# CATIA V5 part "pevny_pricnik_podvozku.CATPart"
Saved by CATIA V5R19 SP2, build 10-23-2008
Part number: pevný příčník podvozku
Bounding box of the stored display mesh (mm): x -30 to 1210, y -1565 to 1565, z -174.111 to 167
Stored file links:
  D:\Catia fórum\Modely - Otazky\Naklapeni_oprava\pevny_pricnik_podvozku.CATPart
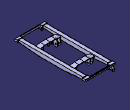
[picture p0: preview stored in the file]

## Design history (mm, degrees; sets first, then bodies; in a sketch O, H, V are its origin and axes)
Body1 (main body)
  Sketch1 on yz-plane, origin (0, 0, 0), H (0, 1, 0), V (0, 0, 1)
    construction line L1 (0, 0) -> (0, 143.6319)
    point P1 (0, 143.6319)
    line L2 (0, 160) -> (-1350, 160)
    point P2 (0, 160)
    point P3 (-1350, 160)
    line L3 (-1350, 160) -> (-1350, 74.3654)
    point P4 (-1350, 74.3654)
    line L4 (-1350, 74.3654) -> (-500, 0)
    point P5 (-500, 0)
    line L5 (-500, 0) -> (0, 0)
    point P6 (0, 143.6319)
    point P7 (0, 160)
    point P8 (0, 0)
    point P9 (500, 0)
    line L6 (500, 0) -> (0, 0)
    point P10 (1350, 74.3654)
    line L7 (1350, 74.3654) -> (500, 0)
    point P11 (1350, 160)
    line L8 (1350, 160) -> (1350, 74.3654)
    line L9 (0, 160) -> (1350, 160)
    distance L3 L1 = 1350
    distance P5 L1 = 500
    distance L5 L2 = 160
    angle L4 L5 = 175
    vertical: L1 V, L3 V
    coincidence: P2 L1, P5 H, O P8, P2 P7
    horizontal: L2 H, L5 H
    symmetry: P1 P6 L1, P2 P7 L1, O P8 L1, P5 P9 L1, L5 L6 L1, P4 P10 L1, L4 L7 L1, P3 P11 L1, L3 L8 L1, L2 L9 L1
  Pad1: profile Sketch1, direction (1, 0, 0), length 140
  Shell1: IntOffset 10, Face face of Pad1 from Sketch1.L9, ExtOffset 0
  Sketch2 on face of Shell1, origin (0, -1340, 0), H (-1, 0, 0), V (0, 0, 1)
    line L1 (-130, 160) -> (-10, 160)
    line L2 (-10, 160) -> (-10, 150)
    line L3 (-10, 150) -> (-130, 150)
    line L4 (-130, 150) -> (-130, 160)
    reference projected line E1 (-10, 160) -> (-130, 160) from edge [face of Pad1 from Sketch1.L2 | face of Shell1]
    reference projected line E2 (-130, 160) -> (-130, 83.5287) from edge [face of Shell1 | face of Shell1]
    reference projected line E3 (-10, 160) -> (-10, 83.5287) from edge [face of Shell1 | face of Shell1]
    distance L3 L1 = 10
    horizontal: L1 H, L3 H
    vertical: L2 V, L4 V
    coincidence: L1 E1, L4 E2, E3 L2
  Pad2: profile Sketch2, direction (0, 1, 0), up to the existing solid (limit type 2)
  Plane1: type Offset, RefPlane face of Pad1 from Sketch1.L3, Offset 550
  Sketch3 on Plane1, origin (0, -800, 0), H (-1, 0, 0), V (0, 0, 1)
    line L1 (-366.8513, 160) -> (-590, 160)
    point P1 (-590, 160)
    point P2 (-590, 140)
    line L2 (-590, 140) -> (-368.601, 140)
    point P3 (-368.601, 140)
    line L3 (-368.601, 140) -> (-140, 99.6915)
    reference projected line E1 (0, 160) -> (-140, 160) from edge [face of Pad1 from Sketch1.L3 | face of Pad1 from Sketch1.L2]
    line L4 (-366.8513, 160) -> (-140, 120)
    point P4 (-366.8513, 160)
    line L5 (-140, 120) -> (-140, 99.6915)
    point P5 (-140, 120)
    point P6 (-140, 99.6915)
    reference projected line E2 (-140, 160) -> (-140, 74.3654) from edge [face of Pad1 from Sketch1.L3 | end face of Pad1]
    construction line L6 (-590, 160) -> (-590, -11.9154)
    point P8 (-590, 160)
    point P9 (-813.1487, 160)
    line L7 (-813.1487, 160) -> (-590, 160)
    point P10 (-811.399, 140)
    point P11 (-590, 140)
    line L8 (-590, 140) -> (-811.399, 140)
    point P12 (-1040, 99.6915)
    line L9 (-811.399, 140) -> (-1040, 99.6915)
    point P13 (-1040, 120)
    line L10 (-813.1487, 160) -> (-1040, 120)
    line L11 (-1040, 120) -> (-1040, 99.6915)
    distance L2 L1 = 20
    distance L3 L4 = 20
    angle L1 L4 = 170
    distance P5 L1 = 40
    distance P2 L5 = 450
    horizontal: L1 H, L2 H
    coincidence: E1 L1, E2 L5, P1 P8, P2 P11
    vertical: L5 V, L6 V
    symmetry: P1 P8 L6, P4 P9 L6, L1 L7 L6, P3 P10 L6, P2 P11 L6, L2 L8 L6, P6 P12 L6, L3 L9 L6, P5 P13 L6, L4 L10 L6, L5 L11 L6
  Pad3: profile Sketch3, direction (0, 1, 0), length 190
  Plane2: type Offset, RefPlane face of Pad1 from Sketch1.L3, Offset 1350
  Mirror1: of Pad3, about Plane2
  Plane3: type 2Lines, Element1 edge [face of Pad3 from Sketch3.L7 | face of Pad3 from Sketch3.L1], Element2 edge [face of Pad3 from Sketch3.L2 | face of Pad3 from Sketch3.L8]
  Mirror2: of Pad1, about Plane3
  Shell2: IntOffset 10, Face face of Mirror2, ExtOffset 0
  Mirror3: of Pad2, about Plane3
  Plane4: type Offset, RefPlane face of Mirror2, Offset 55, reversed
  Sketch4 on Plane4, origin (985, 0, 0), H (0, 1, 0), V (0, 0, 1)
    point P1 (610, 60)
    line L1 (610, 60) -> (590.9881, -47.8217)
    line L2 (772.4683, 60) -> (748.5574, -75.6054)
    reference projected line E1 (610, 98.7164) -> (610, 140) from edge [face of Mirror1 | face of Mirror1]
    line L3 (610, 60) -> (772.4683, 60)
    point P3 (610, 60)
    construction line L4 (709.1227, 161.4509) -> (616.3703, -364.5737)
    construction line L5 (579.7268, -111.6877) -> (721.5262, -136.6907)
    point P6 (579.7268, -111.6877)
    arc A1 centre (664.7851, -90) radius 85 from (590.9881, -47.8217) to (748.5574, -75.6054) ccw
    point P8 (664.7851, -90)
    reference projected line E2 (1350, 160) -> (0, 160) from edge [face of Pad1 from Sketch1.L9 | end face of Pad1]
    reference projected line E3 (1350, 160) -> (0, 160) from edge [face of Pad1 from Sketch1.L9 | end face of Pad1]
    circle A2 centre (664.7851, -90) radius 35
    angle L3 L2 = 80
    distance L1 L2 = 160
    distance L4 L1 = 80
    radius A1 = 85
    distance L3 E2 = 100
    distance P8 E3 = 250
    radius A2 = 35
    coincidence: P1 E1, P3 L1, P1 L3, P6 L1, P8 L4, P1 P3
    horizontal: L3 H
    perpendicularity: L5 L2
  Pad4: profile Sketch4, direction (1, 0, 0), length 30
  Pad5: profile face of Pad4 from Sketch4.L3, direction along edge [start face of Pad4 | face of Pad4 from Sketch4.L2], up to face of Mirror1
  RectPattern1: of Pad4, direction 1 instances 2, spacing 120, along edge [face of Mirror1 | face of Mirror1]
  Pad6: profile face of RectPattern1, direction along edge [face of Pad6 | face of RectPattern1], up to the existing solid (limit type 2)
  Plane5: type 2Lines, Element1 edge [face of Mirror1 | face of Mirror1], Element2 edge [face of Mirror1 | face of Mirror1]
  Mirror4: of Pad4, about Plane5
  Mirror5: of the body so far, about Plane5
  Mirror6: of Pad4, about Plane2
  Mirror7: of the body so far, about Plane2
  Sketch5 on face of Mirror7, origin (0, 0, 140), H (1, 0, 0), V (0, -1, 0)
    point P1 (502.5, 660)
    line L1 (502.5, 660) -> (542.5, 660)
    line L2 (542.5, 660) -> (542.5, 610)
    line L3 (542.5, 610) -> (502.5, 610)
    line L4 (502.5, 610) -> (502.5, 660)
    point P2 (542.5, 660)
    point P3 (542.5, 610)
    point P4 (502.5, 610)
    reference projected line E1 (590, 610) -> (368.601, 610) from edge [face of Mirror7 | face of Mirror7]
    reference projected line E2 (590, 800) -> (590, 610) from edge [face of Mirror7 | face of Mirror7]
    point P7 (637.5, 660)
    point P8 (677.5, 660)
    line L5 (677.5, 660) -> (637.5, 660)
    point P9 (677.5, 610)
    line L6 (677.5, 610) -> (677.5, 660)
    point P10 (637.5, 610)
    line L7 (637.5, 610) -> (677.5, 610)
    line L8 (637.5, 660) -> (637.5, 610)
    construction line L9 (522.5, 743.471) -> (522.5, 588.3346)
    distance L1 L3 = 50
    distance L4 L2 = 40
    distance L9 E2 = 67.5
    distance L9 L2 = 20
    horizontal: L1 H, L3 H
    vertical: L2 V, L4 V, L9 V
    coincidence: L3 E1
    symmetry: P2 P7 E2, P1 P8 E2, L1 L5 E2, P4 P9 E2, L4 L6 E2, P3 P10 E2, L3 L7 E2, L2 L8 E2
  Pad7: profile Sketch5, direction (0, 0, -1), length 100
  Sketch6 on end face of Pad7, origin (522.8217, -674.2765, 40), H (1, 0, 0), V (0, -1, 0)
    point P1 (-0.3217, -39.2765)
    reference projected line E1 (19.6783, -64.2765) -> (19.6783, 35.7235) from edge [face of Pad7 from Sketch5.L2 | end face of Pad7]
    reference projected line E2 (24.6783, -14.2765) -> (-25.3217, -14.2765) from edge [face of Pad7 from Sketch5.L1 | end face of Pad7]
    distance P1 E1 = 20
    distance P1 E2 = 25
  Hole1: placed by Sketch6, at (522.5, -635, 40) direction (0, 0, 1), diameter 21, depth 22
  RectPattern2: of Hole1, direction 1 instances 2, spacing 135, along edge [face of Pad7 from Sketch5.L1 | end face of Pad7] reversed
  Mirror8: of the body so far, about Plane2
  Plane6: type Offset, RefPlane face of Mirror8, Offset 30, reversed
  Sketch7 on Plane6, origin (1210, 0, 0), H (0, -1, 0), V (0, 0, 1)
    line L1 (1350, 167) -> (1350, 67)
    line L2 (1350, 67) -> (1360, 67)
    line L3 (1360, 67) -> (1360, 82)
    line L4 (1360, 82) -> (1463.2198, 82)
    line L5 (1470, 122) -> (1470, 152)
    line L6 (1470, 152) -> (1360, 152)
    line L7 (1360, 152) -> (1360, 167)
    line L8 (1360, 167) -> (1350, 167)
    reference projected line E1 (-1350, 160) -> (1350, 160) from edge [face of Mirror8 | face of Mirror8]
    reference projected line E2 (1350, 160) -> (1350, 74.3654) from edge [face of Mirror8 | face of Mirror8]
    point P8 (1463.2198, 82)
    line L9 (1463.2198, 82) -> (1470.8803, 75.5721)
    line L10 (1470.8803, 75.5721) -> (1493.3778, 102.3837)
    line L11 (1493.3778, 102.3837) -> (1470, 122)
    point P11 (1470, 122)
    distance L6 E1 = 8
    distance L4 L6 = 70
    distance L7 L1 = 10
    distance L8 L6 = 15
    distance L2 L4 = 15
    distance L5 L1 = 120
    distance L10 P8 = 10
    angle L5 L11 = 130
    distance L11 L9 = 35
    distance P11 L6 = 30
    vertical: L1 V, L3 V, L5 V, L7 V
    horizontal: L2 H, L4 H, L6 H, L8 H
    coincidence: L7 L3, L1 E2
    perpendicularity: L10 L9
  Pad8: profile Sketch7, direction (-1, 0, 0), length 200
  RectPattern3: of Pad8, direction 1 instances 2, spacing 1040, along edge [face of Mirror8 | face of Mirror8] reversed
  Sketch8 on end face of Pad8, origin (1010, 0, 0), H (0, -1, 0), V (0, 0, 1)
    line L1 (1493.3778, 102.3837) -> (1470, 122)
    line L2 (1470, 122) -> (1470, 152)
    line L3 (1470, 152) -> (1445, 152)
    line L4 (1445, 152) -> (1445, 82)
    line L5 (1445, 82) -> (1463.2198, 82)
    line L6 (1463.2198, 82) -> (1470.8803, 75.5721)
    line L7 (1470.8803, 75.5721) -> (1493.3778, 102.3837)
    reference projected line E1 (1493.3778, 102.3837) -> (1470, 122) from edge [face of RectPattern3 | face of RectPattern3]
    reference projected line E2 (1470.8803, 75.5721) -> (1493.3778, 102.3837) from edge [face of RectPattern3 | face of RectPattern3]
    reference projected line E3 (1463.2198, 82) -> (1470.8803, 75.5721) from edge [face of RectPattern3 | face of RectPattern3]
    reference projected line E4 (1360, 82) -> (1463.2198, 82) from edge [face of RectPattern3 | face of RectPattern3]
    reference projected line E5 (1470, 152) -> (1360, 152) from edge [face of RectPattern3 | face of RectPattern3]
    reference projected line E6 (1470, 122) -> (1470, 152) from edge [face of RectPattern3 | face of RectPattern3]
    distance L2 L4 = 25
    vertical: L2 V, L4 V
    horizontal: L3 H, L5 H
    parallelism: L6 L1
    perpendicularity: L7 L1
    coincidence: E1 L1, L7 E2, L6 E3, L5 E4, L3 E5, L2 E6
  Pad9: profile Sketch8, direction (-1, 0, 0), up to the existing solid (limit type 2)
  Plane7: type Offset, RefPlane face of RectPattern3, Offset 50, reversed
  Sketch9 on Plane7, origin (0, 0, 32), H (1, 0, 0), V (0, 1, 0)
    line L1 (170, -1390) -> (90, -1390)
    line L2 (90, -1390) -> (90, -1565)
    line L3 (90, -1565) -> (170, -1565)
    line L4 (170, -1565) -> (170, -1390)
    reference projected line E1 (170, -1360) -> (-30, -1360) from edge [face of RectPattern3 | face of RectPattern3]
    reference projected line E2 (170, -1360) -> (170, -1463.2198) from edge [face of RectPattern3 | face of RectPattern3]
    distance L1 E1 = 30
    distance L3 L1 = 175
    distance L4 L2 = 80
    horizontal: L1 H, L3 H
    vertical: L2 V, L4 V
    coincidence: L4 E2
  Pad10: profile Sketch9, direction (0, 0, -1), length 20
  Sketch10 on end face of Pad10, origin (0, 0, 12), H (1, 0, 0), V (0, -1, 0)
    point P1 (90, 1565)
    line L1 (90, 1565) -> (170, 1565)
    line L2 (170, 1565) -> (170, 1525)
    line L3 (170, 1525) -> (90, 1525)
    line L4 (90, 1525) -> (90, 1565)
    point P2 (170, 1565)
    point P3 (170, 1525)
    point P4 (90, 1525)
    construction line L5 (80.7783, 1477.5) -> (208.9645, 1477.5)
    construction line L6 (62.8179, 1545) -> (221.1409, 1545)
    reference projected line E1 (170, 1498.0309) -> (170, 1390) from edge [end face of Pad10 | face of Pad10 from Sketch9.L4]
    reference projected line E2 (90, 1390) -> (90, 1498.0309) from edge [end face of Pad10 | face of Pad10 from Sketch9.L2]
    reference projected line E3 (90, 1565) -> (170, 1565) from edge [end face of Pad10 | face of Pad10 from Sketch9.L3]
    point P9 (90, 1430)
    point P10 (170, 1430)
    line L7 (170, 1430) -> (90, 1430)
    point P11 (90, 1390)
    line L8 (90, 1430) -> (90, 1390)
    point P12 (170, 1390)
    line L9 (90, 1390) -> (170, 1390)
    line L10 (170, 1390) -> (170, 1430)
    distance L6 L5 = 67.5
    distance L3 L6 = 20
    distance L3 L1 = 40
    horizontal: L1 H, L3 H, L5 H, L6 H
    vertical: L2 V, L4 V
    coincidence: E1 L2, E2 L4, L1 E3
    symmetry: P4 P9 L5, P3 P10 L5, L3 L7 L5, P1 P11 L5, L4 L8 L5, P2 P12 L5, L1 L9 L5, L2 L10 L5
  Pad11: profile Sketch10, direction (0, 0, -1), length 50
  Sketch11 on face of Pad11, origin (90, 0, 0), H (0, -1, 0), V (0, 0, 1)
    point P1 (1565, 32)
    line L1 (1565, 32) -> (1493.3778, 102.3837)
    point P2 (1493.3778, 102.3837)
    line L2 (1493.3778, 102.3837) -> (1470.8803, 75.5721)
    line L3 (1470.8803, 75.5721) -> (1463.2198, 82)
    line L4 (1463.2198, 82) -> (1419.1631, 82)
    line L5 (1419.1631, 82) -> (1390.3646, 32)
    line L6 (1390.3646, 32) -> (1565, 32)
    reference projected line E1 (1390, 32) -> (1565, 32) from edge [face of Pad11 | start face of Pad10]
    reference projected line E2 (1470.8803, 75.5721) -> (1493.3778, 102.3837) from edge [face of RectPattern3 | face of RectPattern3]
    reference projected line E3 (1360, 82) -> (1463.2198, 82) from edge [face of RectPattern3 | face of RectPattern3]
    reference projected line E4 (1463.2198, 82) -> (1470.8803, 75.5721) from edge [face of RectPattern3 | face of RectPattern3]
    reference projected line E5 (1493.3778, 102.3837) -> (1470, 122) from edge [face of Pad9 | face of RectPattern3]
    reference projected point E6 (1565, 32) from vertex [face of Pad11 | face of Pad11 | start face of Pad10]
    horizontal: L4 H
    coincidence: L6 E1, L2 E2, L4 E3, L3 E4, P2 E5, P1 E6
  Pad12: profile Sketch11, direction (1, 0, 0), length 80
  Sketch12 on end face of Pad11, origin (137.7668, -1406.1166, -38), H (1, 0, 0), V (0, -1, 0)
    point P1 (-7.7668, 3.8834)
    reference projected line E1 (-47.7668, -16.1166) -> (32.2332, -16.1166) from edge [face of Pad11 | end face of Pad11]
    reference projected line E2 (32.2332, 23.8834) -> (32.2332, -16.1166) from edge [face of Pad12 | end face of Pad11]
    distance P1 E1 = 20
    distance P1 E2 = 40
  Hole2: placed by Sketch12, at (130, -1410, -38) direction (0, 0, 1), diameter 21, depth 22
  Mirror9: of Pad8, Pad9, Pad10, Pad11, Pad12, Hole2, about Plane2
  Mirror10: of Pad9, about Plane2
  Mirror11: of the body so far, about Plane2
  RectPattern4: of Hole2, direction 1 instances 2, spacing 135, along edge [face of Mirror11 | face of Mirror11]
  Sketch13 on face of Mirror11, origin (144.1176, 1544.9664, -38), H (1, 0, 0), V (0, -1, 0)
    point P1 (-14.1176, -0.0336)
    reference projected line E1 (25.8824, 114.9664) -> (25.8824, 154.9664) from edge [face of Mirror11 | face of Mirror9]
    reference projected line E3 (-54.1176, 19.9664) -> (25.8824, 19.9664) from edge [face of Mirror11 | face of Mirror11]
    distance P1 E1 = 40
    distance P1 E3 = 20
  Hole3: placed by Sketch13, at (130, 1545, -38) direction (0, 0, 1), diameter 21, depth 22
